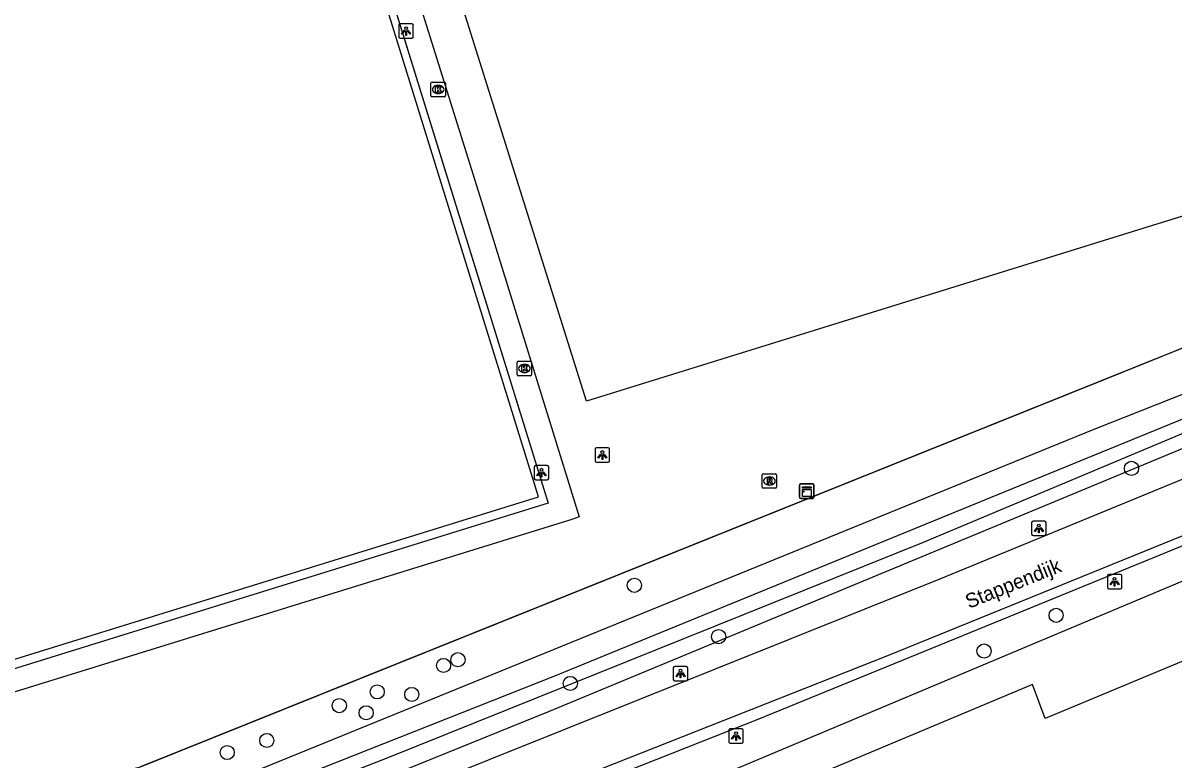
# Model space of a CAD drawing. Extents: x 161094 to 161705, y 379509 to 380907.
# Drawn here: x 161308.9 to 161388.6, y 379764.3 to 379815.3 of the extents above; entities that cross this region are included whole.
import ezdxf

# ---------------------------------------------------------------- set-up
doc = ezdxf.new("R2010")
doc.units = 0
for name, color, linetype in [('IMGEO_Boom', 7, 'Continuous'), ('IMGEO_Fietspad_gesloten', 7, 'Continuous'), ('IMGEO_Groenvoorziening', 7, 'Continuous'), ('IMGEO_Hek', 7, 'Continuous'), ('IMGEO_Kast', 7, 'Continuous'), ('IMGEO_Kolk', 7, 'Continuous'), ('IMGEO_Lichtpunt', 7, 'Continuous'), ('IMGEO_Openbare_ruimte_label', 7, 'Continuous'), ('IMGEO_Parkeervlak_gesloten', 7, 'Continuous'), ('IMGEO_Rijbaan_lokaal_gesloten', 7, 'Continuous'), ('IMGEO_Rioolput', 7, 'Continuous'), ('IMGEO_Voetpad_open', 7, 'Continuous'), ('IMGEO_Waterloop', 7, 'Continuous')]:
    doc.layers.add(name, color=color, linetype=linetype)

msp = doc.modelspace()

# ---------------------------------------------------------------- linework, layer by layer
at = {"layer": 'IMGEO_Boom'}
for centre in [(161385.637, 379784.44), (161351.238, 379776.349), (161380.42, 379774.272), (161357.066, 379772.8), (161375.433, 379771.801), (161339.03, 379771.2), (161338.031, 379770.803), (161346.802, 379769.558), (161333.443, 379768.976), (161335.83, 379768.8), (161330.817, 379768.025), (161332.677, 379767.53), (161325.801, 379765.614), (161323.059, 379764.777)]:
    msp.add_circle(centre, 0.489, dxfattribs=at)
at = {"layer": 'IMGEO_Fietspad_gesloten'}
for points in [[(161210.481, 379725.863), (161210.245, 379726.978), (161204.585, 379725.735), (161202.141, 379725.056), (161199.88, 379730.004), (161200.37, 379730.456), (161211.43, 379731.076), (161230.315, 379734.955), (161294.533, 379750), (161302.182, 379751.792), (161318.2, 379756.091), (161323.089, 379757.248), (161325.661, 379758.067), (161372.453, 379776.813), (161386.356, 379782.534), (161407.443, 379791.212), (161432.033, 379800.962), (161436.35, 379802.535), (161437.461, 379802.835), (161438.334, 379803.07)], [(161214.473, 379726.815), (161214.16, 379727.839), (161217.63, 379728.601), (161261.386, 379738.685), (161308.111, 379750), (161320.623, 379753.03), (161330.613, 379756.284), (161333.8, 379757.687), (161368.776, 379771.487), (161387.909, 379779.27), (161415.666, 379790.561)]]:
    msp.add_lwpolyline(points, dxfattribs=at)
at = {"layer": 'IMGEO_Groenvoorziening'}
for points in [[(161439.346, 379817.487), (161347.925, 379789.089), (161338.143, 379820.234), (161328.846, 379849.835), (161420.503, 379878.307), (161439.346, 379817.487)], [(161284.135, 379755.78), (161317.062, 379763.781), (161383.819, 379790.615), (161442.415, 379814.263)], [(161321.194, 379761.932), (161383.047, 379787.15), (161437.336, 379808.629), (161438.26, 379805.933), (161414.978, 379796.508), (161345.338, 379767.612), (161322.581, 379758.384), (161307.399, 379754.371), (161244.228, 379739.369), (161215.479, 379732.972)], [(161415.916, 379790.022), (161359.784, 379767.053), (161334.748, 379757.161), (161323.449, 379753.122), (161314.492, 379750.449), (161260.228, 379737.49), (161228.423, 379730.143), (161214.473, 379726.815)]]:
    msp.add_lwpolyline(points, dxfattribs=at)
at = {"layer": 'IMGEO_Hek'}
for points in [[(161315.726, 379877.436), (161345.273, 379782.041)], [(161437.337, 379812.165), (161426.879, 379807.924), (161317.062, 379763.781)], [(161415.916, 379790.022), (161359.784, 379767.053), (161334.748, 379757.161), (161323.449, 379753.122), (161314.492, 379750.449), (161260.228, 379737.49), (161228.423, 379730.143), (161214.473, 379726.815)], [(161345.273, 379782.041), (161288.749, 379764.513)]]:
    msp.add_lwpolyline(points, dxfattribs=at)
at = {"layer": 'IMGEO_Kast'}
for p, q in [((161362.74, 379783.367), (161363.581, 379783.367)), ((161363.581, 379783.367), (161362.74, 379783.367)), ((161362.665, 379782.442), (161362.665, 379783.283)), ((161362.665, 379783.283), (161362.665, 379782.442)), ((161363.665, 379783.292), (161363.665, 379782.451)), ((161363.665, 379782.451), (161363.665, 379783.292)), ((161363.59, 379782.367), (161362.749, 379782.367)), ((161362.749, 379782.367), (161363.59, 379782.367))]:
    msp.add_line(p, q, dxfattribs=at)
for points in [[(161362.86, 379783.157), (161363.46, 379783.157), (161363.46, 379783.072), (161362.86, 379783.072), (161362.86, 379783.157)], [(161362.86, 379782.982), (161363.46, 379782.982), (161363.46, 379782.493), (161362.86, 379782.493), (161362.86, 379782.982)]]:
    msp.add_lwpolyline(points, dxfattribs=at)
msp.add_circle((161362.944, 379782.831), 0.0377, dxfattribs=at)
for centre, start, end in [((161362.743, 379783.289), 92.4484, 184.28452), ((161362.743, 379783.289), 92.4484, 184.28452), ((161363.587, 379783.289), 2.4484, 94.28452), ((161363.587, 379783.289), 2.4484, 94.28452), ((161362.743, 379782.445), 182.4484, 274.28452), ((161362.743, 379782.445), 182.4484, 274.28452), ((161363.587, 379782.445), 272.4484, 4.28452), ((161363.587, 379782.445), 272.4484, 4.28452)]:
    msp.add_arc(centre, 0.0779, start, end, dxfattribs=at)
at = {"layer": 'IMGEO_Kolk'}
for p, q in [((161337.161, 379810.234), (161337.161, 379811.086)), ((161337.236, 379811.16), (161338.088, 379811.16)), ((161337.649, 379810.94), (161337.674, 379810.94)), ((161338.162, 379811.086), (161338.162, 379810.234)), ((161338.088, 379810.16), (161337.236, 379810.16)), ((161337.672, 379810.38), (161337.647, 379810.38)), ((161343.125, 379790.93), (161343.125, 379791.782)), ((161343.2, 379791.856), (161344.052, 379791.856)), ((161343.613, 379791.636), (161343.638, 379791.636)), ((161344.126, 379791.782), (161344.126, 379790.93)), ((161344.052, 379790.856), (161343.2, 379790.856)), ((161343.636, 379791.076), (161343.611, 379791.076))]:
    msp.add_line(p, q, dxfattribs=at)
for points in [[(161337.161, 379810.234), (161337.161, 379811.086)], [(161337.236, 379811.16), (161338.088, 379811.16)], [(161337.482, 379810.86), (161337.605, 379810.86), (161337.605, 379810.709), (161337.735, 379810.86), (161337.899, 379810.86), (161337.753, 379810.709), (161337.906, 379810.46), (161337.754, 379810.46), (161337.669, 379810.624), (161337.605, 379810.557), (161337.605, 379810.46), (161337.482, 379810.46), (161337.482, 379810.86)], [(161338.162, 379811.086), (161338.162, 379810.234)], [(161338.088, 379810.16), (161337.236, 379810.16)], [(161343.125, 379790.93), (161343.125, 379791.782)], [(161343.2, 379791.856), (161344.052, 379791.856)], [(161343.446, 379791.556), (161343.569, 379791.556), (161343.569, 379791.405), (161343.699, 379791.556), (161343.863, 379791.556), (161343.717, 379791.405), (161343.87, 379791.156), (161343.718, 379791.156), (161343.633, 379791.32), (161343.569, 379791.253), (161343.569, 379791.156), (161343.446, 379791.156), (161343.446, 379791.556)], [(161344.126, 379791.782), (161344.126, 379790.93)], [(161344.052, 379790.856), (161343.2, 379790.856)]]:
    msp.add_lwpolyline(points, dxfattribs=at)
for centre, start, end in [((161337.238, 379811.084), 91.55205, 178.44795), ((161337.238, 379811.084), 91.55205, 178.44795), ((161338.086, 379811.084), 1.55205, 88.44795), ((161338.086, 379811.084), 1.55205, 88.44795), ((161337.238, 379810.236), 181.55205, 268.44795), ((161337.238, 379810.236), 181.55205, 268.44795), ((161338.086, 379810.236), 271.55205, 358.44795), ((161338.086, 379810.236), 271.55205, 358.44795), ((161343.202, 379791.78), 91.55205, 178.44795), ((161343.202, 379791.78), 91.55205, 178.44795), ((161344.05, 379791.78), 1.55205, 88.44795), ((161344.05, 379791.78), 1.55205, 88.44795), ((161343.202, 379790.932), 181.55205, 268.44795), ((161343.202, 379790.932), 181.55205, 268.44795), ((161344.05, 379790.932), 271.55205, 358.44795), ((161344.05, 379790.932), 271.55205, 358.44795)]:
    msp.add_arc(centre, 0.0765, start, end, dxfattribs=at)
for centre, major_axis, ratio, start_param, end_param in [((161337.648, 379810.66), (-0.387, 0.002), 0.722429, 4.712389, 7.853982), ((161337.673, 379810.66), (-0.39, 0.002), 0.717154, 1.570796, 4.712389), ((161343.612, 379791.356), (-0.387, 0.002), 0.722429, 4.712389, 7.853982), ((161343.637, 379791.356), (-0.39, 0.002), 0.717154, 1.570796, 4.712389)]:
    msp.add_ellipse(centre, major_axis=major_axis, ratio=ratio, start_param=start_param, end_param=end_param, dxfattribs=at)
at = {"layer": 'IMGEO_Lichtpunt'}
for p, q in [((161335.846, 379815.198), (161335.038, 379815.198)), ((161335.846, 379815.198), (161335.038, 379815.198)), ((161334.944, 379815.103), (161334.944, 379814.296)), ((161334.944, 379815.103), (161334.944, 379814.296)), ((161335.94, 379814.296), (161335.94, 379815.103)), ((161335.94, 379814.296), (161335.94, 379815.103)), ((161335.038, 379814.202), (161335.846, 379814.202)), ((161335.038, 379814.202), (161335.846, 379814.202)), ((161348.524, 379785.771), (161348.524, 379784.964)), ((161348.524, 379785.771), (161348.524, 379784.964)), ((161349.426, 379785.866), (161348.618, 379785.866)), ((161349.426, 379785.866), (161348.618, 379785.866)), ((161349.52, 379784.964), (161349.52, 379785.771)), ((161349.52, 379784.964), (161349.52, 379785.771)), ((161344.311, 379784.549), (161344.311, 379783.742)), ((161344.311, 379784.549), (161344.311, 379783.742)), ((161345.213, 379784.644), (161344.405, 379784.644)), ((161345.213, 379784.644), (161344.405, 379784.644)), ((161345.307, 379783.742), (161345.307, 379784.549)), ((161345.307, 379783.742), (161345.307, 379784.549)), ((161348.618, 379784.87), (161349.426, 379784.87)), ((161348.618, 379784.87), (161349.426, 379784.87)), ((161344.405, 379783.648), (161345.213, 379783.648)), ((161344.405, 379783.648), (161345.213, 379783.648)), ((161378.729, 379780.687), (161378.729, 379779.88)), ((161378.729, 379780.687), (161378.729, 379779.88)), ((161379.631, 379780.782), (161378.823, 379780.782)), ((161379.631, 379780.782), (161378.823, 379780.782)), ((161379.725, 379779.88), (161379.725, 379780.687)), ((161379.725, 379779.88), (161379.725, 379780.687)), ((161378.823, 379779.786), (161379.631, 379779.786)), ((161378.823, 379779.786), (161379.631, 379779.786)), ((161383.966, 379777.002), (161383.966, 379776.195)), ((161383.966, 379777.002), (161383.966, 379776.195)), ((161384.868, 379777.097), (161384.06, 379777.097)), ((161384.868, 379777.097), (161384.06, 379777.097)), ((161384.962, 379776.195), (161384.962, 379777.002)), ((161384.962, 379776.195), (161384.962, 379777.002)), ((161384.06, 379776.101), (161384.868, 379776.101)), ((161384.06, 379776.101), (161384.868, 379776.101)), ((161353.932, 379770.645), (161353.932, 379769.838)), ((161353.932, 379770.645), (161353.932, 379769.838)), ((161354.834, 379770.74), (161354.026, 379770.74)), ((161354.834, 379770.74), (161354.026, 379770.74)), ((161354.928, 379769.838), (161354.928, 379770.645)), ((161354.928, 379769.838), (161354.928, 379770.645)), ((161354.026, 379769.744), (161354.834, 379769.744)), ((161354.026, 379769.744), (161354.834, 379769.744)), ((161357.772, 379766.323), (161357.772, 379765.516)), ((161357.772, 379766.323), (161357.772, 379765.516)), ((161358.674, 379766.418), (161357.866, 379766.418)), ((161358.674, 379766.418), (161357.866, 379766.418)), ((161358.768, 379765.516), (161358.768, 379766.323)), ((161358.768, 379765.516), (161358.768, 379766.323)), ((161357.866, 379765.422), (161358.674, 379765.422)), ((161357.866, 379765.422), (161358.674, 379765.422))]:
    msp.add_line(p, q, dxfattribs=at)
for points in [[(161335.318, 379814.767), (161335.357, 379814.739), (161335.169, 379814.477), (161335.131, 379814.504), (161335.318, 379814.767)], [(161335.42, 379814.719), (161335.467, 379814.719), (161335.467, 379814.397), (161335.42, 379814.397), (161335.42, 379814.719)], [(161335.53, 379814.739), (161335.568, 379814.766), (161335.755, 379814.504), (161335.716, 379814.476), (161335.53, 379814.739)], [(161348.898, 379785.435), (161348.937, 379785.407), (161348.749, 379785.145), (161348.711, 379785.172), (161348.898, 379785.435)], [(161349, 379785.387), (161349.047, 379785.387), (161349.047, 379785.065), (161349, 379785.065), (161349, 379785.387)], [(161349.11, 379785.407), (161349.148, 379785.434), (161349.335, 379785.172), (161349.296, 379785.144), (161349.11, 379785.407)], [(161344.685, 379784.213), (161344.724, 379784.185), (161344.536, 379783.923), (161344.498, 379783.95), (161344.685, 379784.213)], [(161344.787, 379784.165), (161344.834, 379784.165), (161344.834, 379783.843), (161344.787, 379783.843), (161344.787, 379784.165)], [(161344.897, 379784.185), (161344.935, 379784.212), (161345.122, 379783.95), (161345.083, 379783.922), (161344.897, 379784.185)], [(161379.103, 379780.351), (161379.142, 379780.323), (161378.954, 379780.061), (161378.916, 379780.088), (161379.103, 379780.351)], [(161379.205, 379780.303), (161379.252, 379780.303), (161379.252, 379779.981), (161379.205, 379779.981), (161379.205, 379780.303)], [(161379.315, 379780.323), (161379.353, 379780.35), (161379.54, 379780.088), (161379.501, 379780.06), (161379.315, 379780.323)], [(161384.34, 379776.666), (161384.379, 379776.638), (161384.191, 379776.376), (161384.153, 379776.403), (161384.34, 379776.666)], [(161384.442, 379776.618), (161384.489, 379776.618), (161384.489, 379776.296), (161384.442, 379776.296), (161384.442, 379776.618)], [(161384.552, 379776.638), (161384.59, 379776.665), (161384.777, 379776.403), (161384.738, 379776.375), (161384.552, 379776.638)], [(161354.306, 379770.309), (161354.345, 379770.281), (161354.157, 379770.019), (161354.119, 379770.046), (161354.306, 379770.309)], [(161354.408, 379770.261), (161354.455, 379770.261), (161354.455, 379769.939), (161354.408, 379769.939), (161354.408, 379770.261)], [(161354.518, 379770.281), (161354.556, 379770.308), (161354.743, 379770.046), (161354.704, 379770.018), (161354.518, 379770.281)], [(161358.146, 379765.987), (161358.185, 379765.959), (161357.997, 379765.697), (161357.959, 379765.724), (161358.146, 379765.987)], [(161358.248, 379765.939), (161358.295, 379765.939), (161358.295, 379765.617), (161358.248, 379765.617), (161358.248, 379765.939)], [(161358.358, 379765.959), (161358.396, 379765.986), (161358.583, 379765.724), (161358.544, 379765.696), (161358.358, 379765.959)]]:
    msp.add_lwpolyline(points, dxfattribs=at)
for centre in [(161335.443, 379814.901), (161349.023, 379785.569), (161344.81, 379784.347), (161379.228, 379780.485), (161384.465, 379776.8), (161354.431, 379770.443), (161358.271, 379766.121)]:
    msp.add_circle(centre, 0.0994, dxfattribs=at)
for centre, start, end in [((161335.038, 379815.103), 90, 180), ((161335.038, 379815.103), 90, 180), ((161335.846, 379815.103), 0, 90), ((161335.846, 379815.103), 0, 90), ((161335.038, 379814.296), 180, 270), ((161335.038, 379814.296), 180, 270), ((161335.846, 379814.296), 270, 0), ((161335.846, 379814.296), 270, 360), ((161348.618, 379785.771), 90, 180), ((161348.618, 379785.771), 90, 180), ((161349.426, 379785.771), 0, 90), ((161349.426, 379785.771), 0, 90), ((161348.618, 379784.964), 180, 270), ((161348.618, 379784.964), 180, 270), ((161349.426, 379784.964), 270, 0), ((161349.426, 379784.964), 270, 360), ((161344.405, 379784.549), 90, 180), ((161344.405, 379784.549), 90, 180), ((161345.213, 379784.549), 0, 90), ((161345.213, 379784.549), 0, 90), ((161344.405, 379783.742), 180, 270), ((161344.405, 379783.742), 180, 270), ((161345.213, 379783.742), 270, 0), ((161345.213, 379783.742), 270, 360), ((161378.823, 379780.687), 90, 180), ((161378.823, 379780.687), 90, 180), ((161379.631, 379780.687), 0, 90), ((161379.631, 379780.687), 0, 90), ((161378.823, 379779.88), 180, 270), ((161378.823, 379779.88), 180, 270), ((161379.631, 379779.88), 270, 0), ((161379.631, 379779.88), 270, 360), ((161384.06, 379777.002), 90, 180), ((161384.06, 379777.002), 90, 180), ((161384.868, 379777.002), 0, 90), ((161384.868, 379777.002), 0, 90), ((161384.06, 379776.195), 180, 270), ((161384.06, 379776.195), 180, 270), ((161384.868, 379776.195), 270, 0), ((161384.868, 379776.195), 270, 360), ((161354.026, 379770.645), 90, 180), ((161354.026, 379770.645), 90, 180), ((161354.834, 379770.645), 0, 90), ((161354.834, 379770.645), 0, 90), ((161354.026, 379769.838), 180, 270), ((161354.026, 379769.838), 180, 270), ((161354.834, 379769.838), 270, 0), ((161354.834, 379769.838), 270, 360), ((161357.866, 379766.323), 90, 180), ((161357.866, 379766.323), 90, 180), ((161358.674, 379766.323), 0, 90), ((161358.674, 379766.323), 0, 90), ((161357.866, 379765.516), 180, 270), ((161357.866, 379765.516), 180, 270), ((161358.674, 379765.516), 270, 0), ((161358.674, 379765.516), 270, 360)]:
    msp.add_arc(centre, 0.0946, start, end, dxfattribs=at)
at = {"layer": 'IMGEO_Parkeervlak_gesloten'}
msp.add_lwpolyline([(161350.416, 379760.36), (161396.996, 379779.937), (161416.941, 379788.17), (161442.348, 379786.735), (161442.363, 379783.593)], dxfattribs=at)
at = {"layer": 'IMGEO_Rijbaan_lokaal_gesloten'}
msp.add_lwpolyline([(161442.797, 379783.132), (161442.331, 379782.871), (161417.67, 379784.271), (161405.758, 379779.385), (161406.243, 379778.203), (161379.671, 379767.143), (161378.797, 379769.491), (161351.281, 379757.944), (161350.416, 379760.36)], dxfattribs=at)
at = {"layer": 'IMGEO_Rioolput'}
for p, q in [((161360.081, 379783.14), (161360.081, 379783.992)), ((161360.156, 379784.066), (161361.008, 379784.066)), ((161360.569, 379783.846), (161360.594, 379783.846)), ((161361.082, 379783.992), (161361.082, 379783.14)), ((161361.008, 379783.066), (161360.156, 379783.066)), ((161360.592, 379783.286), (161360.567, 379783.286))]:
    msp.add_line(p, q, dxfattribs=at)
for points in [[(161360.081, 379783.14), (161360.081, 379783.992)], [(161360.156, 379784.066), (161361.008, 379784.066)], [(161360.67, 379783.764), (161360.418, 379783.766), (161360.418, 379783.366)], [(161360.418, 379783.366), (161360.542, 379783.366), (161360.542, 379783.528), (161360.553, 379783.528)], [(161360.596, 379783.685), (161360.542, 379783.685), (161360.542, 379783.604)], [(161360.542, 379783.604), (161360.594, 379783.604)], [(161360.6, 379783.499), (161360.671, 379783.366), (161360.811, 379783.366), (161360.746, 379783.492)], [(161361.082, 379783.992), (161361.082, 379783.14)], [(161361.008, 379783.066), (161360.156, 379783.066)]]:
    msp.add_lwpolyline(points, dxfattribs=at)
for centre, radius, start, end in [((161360.158, 379783.99), 0.0765, 91.55205, 178.44795), ((161360.158, 379783.99), 0.0765, 91.55205, 178.44795), ((161360.552, 379783.475), 0.0533, 26.02933, 88.69889), ((161360.578, 379783.793), 0.19, 274.7715, 282.96867), ((161360.602, 379783.589), 0.0964, 77.00612, 93.18647), ((161360.616, 379783.646), 0.0378, 276.66336, 79.67722), ((161360.669, 379783.654), 0.109, 350.36119, 89.41601), ((161360.667, 379783.654), 0.112, 277.58423, 350.98172), ((161360.651, 379783.439), 0.108, 29.51342, 73.79051), ((161361.006, 379783.99), 0.0765, 1.55205, 88.44795), ((161361.006, 379783.99), 0.0765, 1.55205, 88.44795), ((161360.158, 379783.142), 0.0765, 181.55205, 268.44795), ((161360.158, 379783.142), 0.0765, 181.55205, 268.44795), ((161361.006, 379783.142), 0.0765, 271.55205, 358.44795), ((161361.006, 379783.142), 0.0765, 271.55205, 358.44795)]:
    msp.add_arc(centre, radius, start, end, dxfattribs=at)
for centre, major_axis, ratio, start_param, end_param in [((161360.568, 379783.566), (-0.387, 0.002), 0.722429, 4.712389, 7.853982), ((161360.593, 379783.566), (-0.39, 0.002), 0.717154, 1.570796, 4.712389)]:
    msp.add_ellipse(centre, major_axis=major_axis, ratio=ratio, start_param=start_param, end_param=end_param, dxfattribs=at)
at = {"layer": 'IMGEO_Voetpad_open'}
for points in [[(161315.4, 379876.688), (161259.804, 379859.465), (161288.984, 379765.251), (161344.596, 379782.479), (161315.4, 379876.688)], [(161323.473, 379857.884), (161325.421, 379851.624), (161340.534, 379803.282), (161347.426, 379781.085), (161346.908, 379780.9), (161282.797, 379761.057)], [(161321.936, 379857.387), (161345.273, 379782.041), (161288.749, 379764.513)]]:
    msp.add_lwpolyline(points, dxfattribs=at)
at = {"layer": 'IMGEO_Waterloop'}
msp.add_lwpolyline([(161209.828, 379734.106), (161253.524, 379743.962), (161280.711, 379750.533), (161313.565, 379758.418), (161319.274, 379759.897), (161322.067, 379760.718), (161345.722, 379770.082), (161377.919, 379783.264), (161415.988, 379798.829), (161436.933, 379807.33), (161437.303, 379806.344), (161408.802, 379795.092), (161371.225, 379779.322), (161334.181, 379764.414), (161322.108, 379759.712), (161320.444, 379759.342), (161312.949, 379757.494), (161293.093, 379752.607), (161257.077, 379743.942), (161210.131, 379732.941)], dxfattribs=at)

# ---------------------------------------------------------------- texts
at = {"layer": 'IMGEO_Openbare_ruimte_label'}
msp.add_text('Stappendijk', height=1, rotation=21.89715, dxfattribs=at).set_placement((161374.388, 379774.715))

doc.saveas('drawing.dxf')
